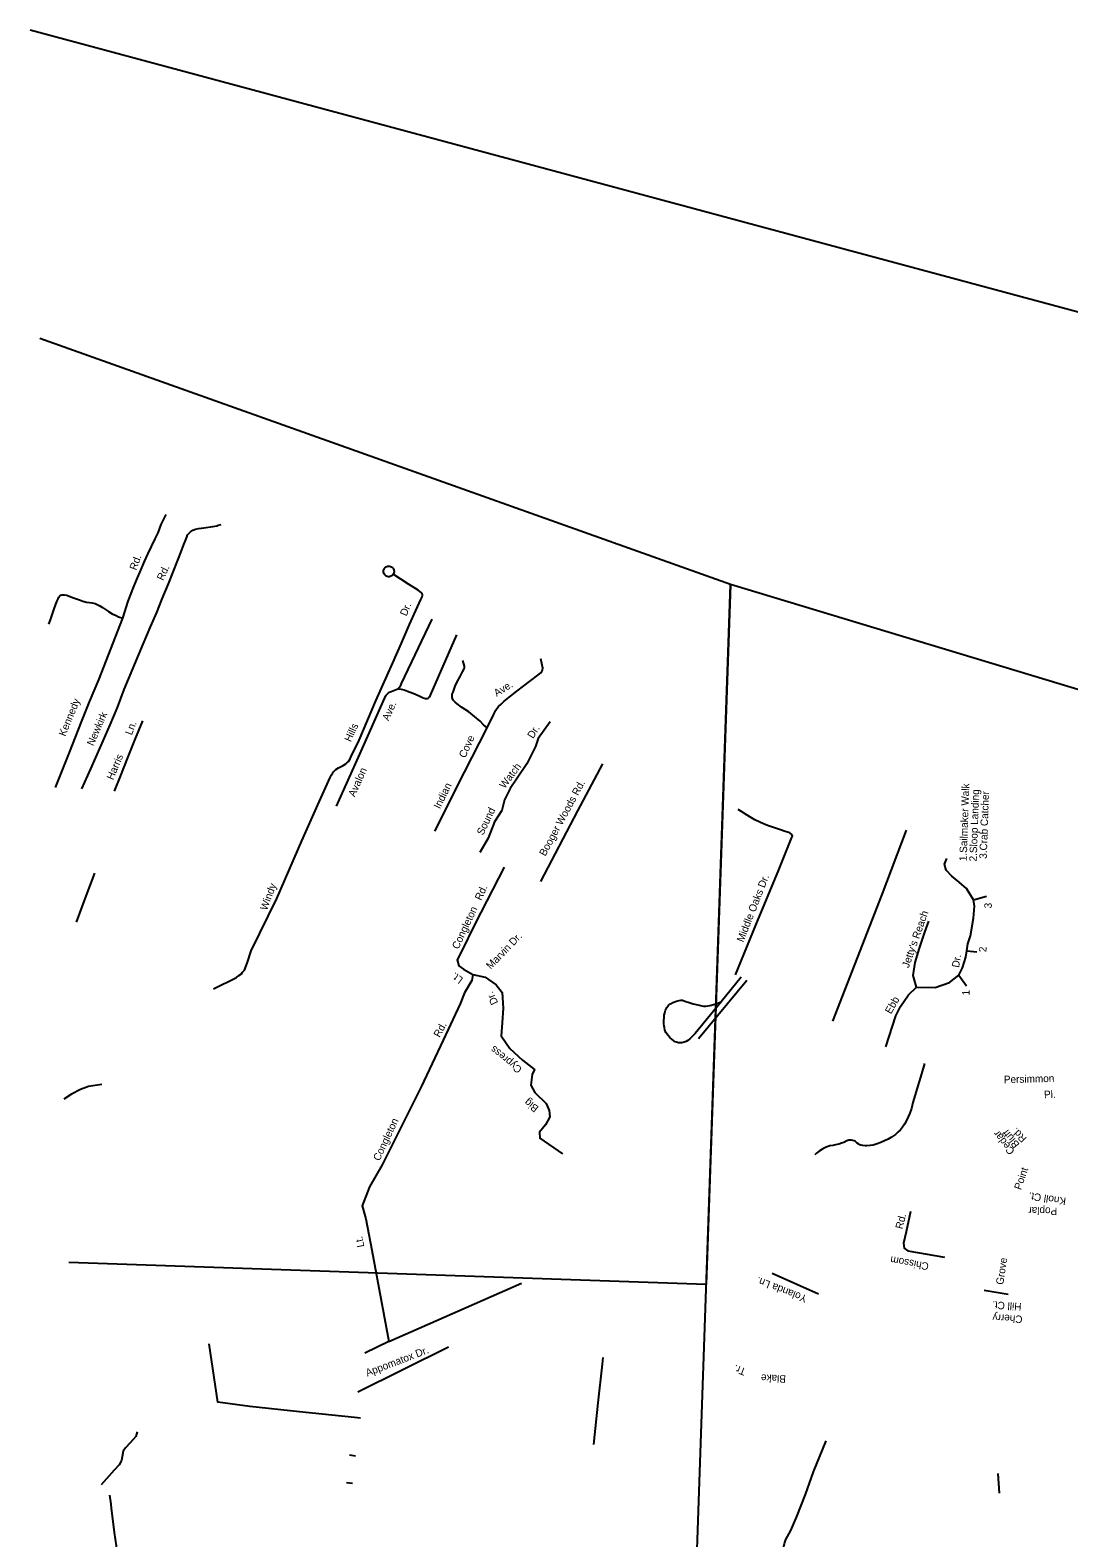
# Model space of a CAD drawing. Extents: x 2308163 to 2335412, y -96774 to 127732.
# Drawn here: x 2317411 to 2319692, y -13815 to -10505 of the extents above; entities that cross this region are included whole.
import ezdxf

# ---------------------------------------------------------------- set-up
doc = ezdxf.new("R2010")
doc.units = 0
for name, color, linetype in [('Old_Level_10', 7, 'Continuous'), ('Old_Level_35', 7, 'Continuous'), ('Old_Level_63', 7, 'Continuous')]:
    doc.layers.add(name, color=color, linetype=linetype)

msp = doc.modelspace()

# ---------------------------------------------------------------- linework, layer by layer
at = {"layer": 'Old_Level_35'}
for p, q in [((2318878.5, -12718.9), (2318984.6, -12590.9)), ((2318972.3, -12584.6), (2318928.5, -12638.1)), ((2318136.5, -13552.3), (2318123, -13551)), ((2318125.4, -13636.1), (2318112.4, -13633.7)), ((2317578.5, -13685.8), (2317566.8, -13698.8)), ((2318119, -13695.9), (2318106, -13694.6)), ((2319536.2, -13673.8), (2319538.9, -13716.9)), ((2317585.5, -13721.4), (2317587.9, -13741.7))]:
    msp.add_line(p, q, dxfattribs=at)
for points in [[(2317614.5, -11795.8), (2317626, -11758.6), (2317637.8, -11729), (2317644.8, -11712.6), (2317654, -11690.3), (2317662, -11671.6), (2317669, -11655.3), (2317685.4, -11621.7), (2317691.8, -11608.8), (2317698.9, -11590.1), (2317709.5, -11568.3)], [(2317524.4, -12170.7), (2317544.2, -12126.6), (2317565.9, -12077), (2317586.7, -12030), (2317603.1, -11991.8), (2317617.3, -11952.8), (2317659.3, -11853.2), (2317675.5, -11815), (2317688.8, -11783.4), (2317701.2, -11753.2), (2317714.7, -11720.6), (2317727.1, -11688.9), (2317741.5, -11651.9), (2317748.4, -11634.4), (2317751.9, -11625.6), (2317754.7, -11618.2), (2317756.8, -11613.3), (2317759.9, -11609.3), (2317763, -11606.4), (2317768, -11603), (2317774.2, -11600.7), (2317780.7, -11599.3), (2317787.4, -11598.4), (2317797.2, -11597.2), (2317807.2, -11595.6), (2317812.2, -11594.6), (2317820.6, -11593.1), (2317824.1, -11592.1), (2317830.7, -11590.2)], [(2318208.5, -11699.4), (2318206.9, -11701.5), (2318205.2, -11702.9), (2318203, -11704.1), (2318200.4, -11704.9), (2318197.6, -11704.9), (2318195.1, -11704.4), (2318193.1, -11703.5), (2318191.2, -11702.2), (2318189.7, -11700.7), (2318188.4, -11698.8), (2318187.6, -11697.1), (2318187.2, -11695.2), (2318187, -11693.2), (2318187.2, -11691.5), (2318187.6, -11689.5), (2318188.5, -11687.8), (2318189.6, -11686.1), (2318190.9, -11684.8), (2318192.4, -11683.6), (2318194.1, -11682.7), (2318195.7, -11682.1), (2318198, -11681.7), (2318200.2, -11681.9), (2318202.5, -11682.3), (2318204.3, -11683.1), (2318205.8, -11684.3), (2318207, -11685.2), (2318208.1, -11686.6), (2318209, -11687.9), (2318209.6, -11689.5), (2318210, -11691.2), (2318210.2, -11692.8), (2318210.2, -11694.6), (2318209.9, -11696.2), (2318209.4, -11697.8), (2318208.5, -11699.4)], [(2318042.9, -12206), (2318069.5, -12145.7), (2318072.6, -12139.7), (2318074.7, -12136.8), (2318076.7, -12133.8), (2318079.3, -12130.9), (2318082.4, -12128), (2318088, -12124.6), (2318098.1, -12119.3), (2318104.2, -12116), (2318106.7, -12113.9), (2318110.1, -12110.5), (2318113.4, -12105.2), (2318114.9, -12101.5), (2318133.3, -12064.2), (2318170, -11977.5), (2318207.6, -11894.2), (2318226.2, -11851), (2318244.1, -11809.9), (2318257.7, -11779.3), (2318268.6, -11754.7), (2318271.6, -11748.8), (2318272.3, -11745.6), (2318271.5, -11742.1), (2318269.7, -11739.8), (2318262.8, -11734.8), (2318242.1, -11721.6), (2318208.5, -11699.4)], [(2317452, -11809.2), (2317455.3, -11799.3), (2317462.8, -11777.5), (2317467.2, -11765.2), (2317470.1, -11757.8), (2317472.1, -11753.2), (2317474.1, -11749.8), (2317476.1, -11747.2), (2317478, -11745.8), (2317480.6, -11744.8), (2317482.3, -11744.6), (2317486, -11744.7), (2317491.1, -11745.7), (2317504.1, -11750.6), (2317519, -11756), (2317526.9, -11758.9), (2317534.8, -11761), (2317541.3, -11761.7), (2317547.1, -11762.4), (2317553.8, -11764.1), (2317558.2, -11765.7), (2317564.1, -11768.9), (2317570.1, -11772.8), (2317574, -11775.7), (2317582.8, -11781.5), (2317590.7, -11786.2), (2317599.6, -11790.4), (2317605, -11793.1), (2317614.5, -11795.8)], [(2317466.4, -12167.5), (2317497.1, -12090.8), (2317523.7, -12023.7), (2317541, -11979.7), (2317561.8, -11931.6), (2317614.5, -11795.8)], [(2318218.7, -11951.2), (2318221.9, -11947.6), (2318224.9, -11943.3), (2318226.5, -11939.8), (2318293.7, -11798.5)], [(2318218.7, -11951.2), (2318226.1, -11952), (2318232.1, -11953.5), (2318239.6, -11956.2), (2318253.5, -11961.5), (2318265.3, -11966.8), (2318274.3, -11971.1), (2318279.1, -11972.2), (2318282.7, -11972.3), (2318285, -11971.5), (2318286.6, -11970.5), (2318288.4, -11968.4), (2318289.9, -11965.4), (2318347.9, -11832.8)], [(2318414.3, -12037), (2318406.9, -12030.3), (2318399.1, -12022.5), (2318386.8, -12012.2), (2318374.1, -12001.9), (2318358.3, -11991.1), (2318348.5, -11984.3), (2318344, -11980.6), (2318341.6, -11977.6), (2318340.2, -11975.9), (2318338.2, -11972.6), (2318337.8, -11970.1), (2318337.4, -11967), (2318338, -11963.1), (2318339.6, -11958.5), (2318342.2, -11951.6), (2318344.5, -11945.6), (2318349.1, -11935.9), (2318355, -11923.9), (2318360.7, -11913.6), (2318363.8, -11907.2), (2318364.8, -11904), (2318364.9, -11901.2), (2318360.9, -11888.8)], [(2318414.3, -12037), (2318429, -12006.8), (2318433.7, -11997.9), (2318436.5, -11993.6), (2318439.8, -11989.8), (2318445.1, -11984.6), (2318451.7, -11978.3), (2318479.7, -11956.5), (2318525.6, -11921.5), (2318532.3, -11915.8), (2318534.4, -11913), (2318536.4, -11909.8), (2318537.1, -11905.8), (2318532.6, -11885.2)], [(2318083.4, -12209), (2318134.7, -12094.7), (2318189.7, -11970.9), (2318191.5, -11967.1), (2318192.6, -11965.4), (2318193.7, -11964.2), (2318195.1, -11962.5), (2318196.9, -11960.6), (2318198, -11959.8), (2318200.2, -11958.6), (2318218.7, -11951.2)], [(2317596.4, -12175.9), (2317608.3, -12145.3), (2317626.1, -12100.7), (2317640.9, -12064.1), (2317658.1, -12021.6)], [(2318299.7, -12263.7), (2318364.9, -12134.3), (2318414.3, -12037)], [(2318552.8, -12023.8), (2318526.4, -12060.5), (2318520.8, -12077.9), (2318501.9, -12116.1), (2318479.4, -12149.2), (2318464.8, -12170.1), (2318452.7, -12194.7), (2318446.8, -12218.4), (2318430.9, -12242.9), (2318417.1, -12278.8), (2318398.3, -12310.8)], [(2318532.6, -12373.9), (2318613.4, -12218.8), (2318669, -12116.1)], [(2317896.6, -12526.3), (2317952.5, -12411.4), (2318007.5, -12284.7), (2318042.9, -12206)], [(2318959.9, -12578.8), (2319004.5, -12470.3), (2319055, -12348.5), (2319083.3, -12278.7), (2319085.3, -12274.7), (2319083.9, -12271.2), (2319079.5, -12267.6), (2319074.5, -12266), (2319069.1, -12264.3), (2319059.2, -12260.6), (2319030.4, -12250.9), (2319024.9, -12249.3), (2319021.5, -12247.6), (2319013.6, -12244), (2319002.6, -12238.6), (2318991.8, -12232.5), (2318966.2, -12216.4)], [(2319173.5, -12681), (2319281.9, -12402.5), (2319335.3, -12261.7)], [(2318452.2, -12342.7), (2318388.6, -12466.4), (2318356.7, -12530.7), (2318348.8, -12546.5), (2318352.1, -12559), (2318362.9, -12566.8), (2318383.5, -12578.6), (2318410.5, -12584.4), (2318434.6, -12601.3), (2318447.6, -12617.8), (2318450.1, -12652.5), (2318447.8, -12684.5), (2318445.6, -12712.8), (2318464.4, -12740.6), (2318491.9, -12766.3), (2318512, -12781.5)], [(2319290.3, -12737), (2319312.5, -12669.5), (2319322.6, -12648.5), (2319340.2, -12623.1), (2319357.5, -12606.1), (2319398.3, -12606.6), (2319430.3, -12595.6), (2319450.3, -12579.6), (2319458.3, -12564.1), (2319465.6, -12540.2), (2319467.9, -12526.4), (2319470.3, -12510.7), (2319476.5, -12493.3), (2319482.5, -12454.5), (2319485.3, -12428.6), (2319482.9, -12414.6), (2319467.1, -12389.9), (2319450.9, -12375.4), (2319435.5, -12362.8), (2319423, -12349.4), (2319418.8, -12336.3), (2319423.9, -12323.5)], [(2317551.9, -12356), (2317531.9, -12409.8), (2317511.7, -12463.3)], [(2319482.9, -12414.6), (2319511.4, -12406.2)], [(2319357.5, -12606.1), (2319350, -12580.8), (2319354.7, -12552.2), (2319364.1, -12520.9), (2319375.6, -12485.1), (2319384.7, -12461.3)], [(2317813.7, -12610.2), (2317864.1, -12585.1), (2317869.4, -12580.9), (2317874.8, -12577.2), (2317877.5, -12573.3), (2317881.6, -12569.1), (2317887.4, -12553.2), (2317896.6, -12526.3)], [(2319467.9, -12526.4), (2319490.3, -12528.5)], [(2318383.5, -12578.6), (2318380.9, -12591.5), (2318365.2, -12618.6), (2318355.5, -12642.8), (2318318.2, -12722.3), (2318269.4, -12824.9), (2318183.7, -12996.2), (2318156.4, -13044.5), (2318140.2, -13086.2), (2318148.1, -13115.1), (2318161.5, -13183.4)], [(2319450.3, -12579.6), (2319467.6, -12603.5)], [(2318928.5, -12638.1), (2318871.8, -12707.7), (2318865.1, -12714.5), (2318859.9, -12719.4), (2318855.4, -12723.4), (2318852, -12725.6), (2318847.3, -12727.1), (2318842.2, -12728.2), (2318835.2, -12728.3), (2318830.8, -12727.3), (2318827.7, -12726.2), (2318820.8, -12721.3), (2318816.1, -12716.9), (2318812, -12712.4), (2318807, -12705.4), (2318804.9, -12699.6), (2318804, -12695.6), (2318803.6, -12692.1), (2318802.7, -12686.1), (2318802.5, -12679.7), (2318803, -12673), (2318803.7, -12668), (2318804.7, -12662.5), (2318806.5, -12657), (2318809.4, -12651), (2318811.2, -12647.8), (2318813.2, -12645.8), (2318817.3, -12642.9), (2318822.4, -12640), (2318830.5, -12637.2), (2318836, -12635.3), (2318840, -12634.5), (2318843.5, -12635), (2318848.9, -12636.7), (2318858.1, -12640.2), (2318867, -12643.1), (2318877.3, -12645.3), (2318885.9, -12647.1), (2318889.8, -12647.6), (2318895.2, -12647.7), (2318903.3, -12646.5), (2318914.9, -12643.2), (2318928.5, -12638.1)], [(2319375.4, -12773.9), (2319368.3, -12796.7), (2319363.4, -12813.1), (2319349.3, -12859.3), (2319346.5, -12872.8), (2319342.8, -12883.2), (2319339.5, -12891.1), (2319335.6, -12898.6), (2319331.2, -12906.9), (2319327, -12913.3), (2319322.4, -12919.2), (2319316.5, -12924.9), (2319311.1, -12929.9), (2319302.9, -12935.2), (2319295.2, -12939.7), (2319287.4, -12943.6), (2319279.4, -12947.3), (2319271.5, -12950.4), (2319262.4, -12952.9), (2319256.1, -12953.9), (2319248.5, -12954.4), (2319244.7, -12954.5), (2319240, -12954.2), (2319235.5, -12953.1), (2319233.3, -12952.1)], [(2318512, -12781.5), (2318518.4, -12786.9), (2318513.1, -12797.9), (2318510.4, -12821.5), (2318519.1, -12837.6), (2318544.2, -12861.9), (2318551.1, -12877), (2318551.9, -12890.6), (2318542.6, -12908.8), (2318529.7, -12924.4), (2318530.5, -12938), (2318580, -12971.8)], [(2317568.4, -12819.6), (2317539.3, -12824.6), (2317521.5, -12830.8), (2317501.7, -12840.8), (2317484.9, -12852.3)], [(2319233.3, -12952.1), (2319231.2, -12951.1), (2319227.1, -12948.4), (2319222.5, -12944.5), (2319220.3, -12943.4), (2319217.8, -12942.5), (2319213.8, -12942), (2319208.8, -12942.4), (2319204.2, -12943.9), (2319197.6, -12947.2), (2319192.6, -12949), (2319187.2, -12950.7), (2319180, -12952.3), (2319174, -12953.6), (2319167.4, -12954.9), (2319159, -12957.6), (2319151.8, -12961), (2319144.1, -12966.4), (2319138, -12970.7), (2319133.9, -12974.2)], [(2319344.2, -13098.5), (2319334.8, -13143.1), (2319329, -13168.3), (2319330.6, -13179.1), (2319338.2, -13185.3), (2319418.9, -13198.8)], [(2318161.5, -13183.4), (2318198.9, -13384.1), (2318145.8, -13409.9)], [(2319040.3, -13234.3), (2319142, -13279.4)], [(2318198.9, -13384.1), (2318489.9, -13256.4)], [(2319559.2, -13281.2), (2319506.1, -13272.5)], [(2318123, -13551), (2318002.7, -13538.5), (2317893.5, -13526.9), (2317823.1, -13517.7), (2317803.7, -13389.2)], [(2318130.8, -13494.6), (2318329.6, -13396)], [(2318668.9, -13419.1), (2318667.2, -13433.8), (2318657.5, -13518.8), (2318648.3, -13610.2)], [(2317646, -13582.5), (2317643.1, -13593.1), (2317630.6, -13606.6), (2317620.2, -13617.7), (2317615.2, -13625.2), (2317613.3, -13637.1), (2317611.4, -13645.2), (2317606.4, -13654.7), (2317595.5, -13666.8), (2317578.5, -13685.8)], [(2319065.6, -13837.6), (2319067.4, -13827.6), (2319070.7, -13818.6), (2319081.2, -13799.3), (2319094.4, -13768.8), (2319113.5, -13720.3), (2319131.1, -13670.2), (2319159.1, -13602.4)], [(2317587.9, -13741.7), (2317588.9, -13749.8), (2317595.6, -13803.7), (2317603.9, -13862.2), (2317608.6, -13901.1), (2317608.2, -13914.1), (2317603.3, -13926.6), (2317591.4, -13943.2), (2317578.9, -13955.8)]]:
    msp.add_lwpolyline(points, dxfattribs=at)
at = {"layer": 'Old_Level_63'}
for p, q in [((2318948.8, -11722.3), (2317432.2, -11182)), ((2320981.2, -12335.3), (2318948.8, -11722.3))]:
    msp.add_line(p, q, dxfattribs=at)
for points in [[(2324171.2, -12419.9), (2323510.7, -12146.1), (2317410.9, -10504.9)], [(2318948.8, -11722.6), (2318895.8, -13259.4), (2317496.2, -13211.1)], [(2320981.2, -12335.3), (2320867.9, -15621.3), (2318816.5, -15556.5), (2318948.8, -11722.3)]]:
    msp.add_lwpolyline(points, dxfattribs=at)

# ---------------------------------------------------------------- texts
at = {"layer": 'Old_Level_10'}
for s, height, rotation, p in [('Rd.', 16.4, 69.6167, (2317643.8, -11692)), ('Rd.', 16.4, 65.0847, (2317703, -11714.7)), ('Dr.', 16.4, 67.3169, (2318237.4, -11792.7)), ('Ave.', 16.4, 32.0499, (2318435.6, -11969)), ('Kennedy', 16.4, 67.8467, (2317488, -12056.8)), ('Ave.', 16.4, 66.0506, (2318198, -12022.8)), ('Newkirk', 16.4, 66.499, (2317549.7, -12077.7)), ('Ln.', 16.4, 69.1108, (2317634.1, -12054)), ('Hills', 16.4, 65.6411, (2318115, -12069)), ('Dr.', 16.4, 57.3171, (2318515.3, -12061.7)), ('Cove', 16.4, 65.514, (2318366.5, -12104.3)), ('Harris', 16.4, 67.3307, (2317593.2, -12152.5)), ('Avalon', 16.4, 65.8193, (2318123.5, -12189.8)), ('Watch', 16.4, 53.1139, (2318453.1, -12171.5)), ('Indian ', 16.4, 63.7995, (2318310.9, -12216)), ('Booger Woods Rd.', 16.404, 61.6242, (2318542.3, -12319.9)), ('1.Sailmaker Walk', 16.404, 88.0247, (2319467.8, -12329.8)), ('2.Sloop Landing', 16.404, 88.0247, (2319489.8, -12330.4)), ('3.Crab Catcher', 16.404, 88.0247, (2319511.8, -12324.6)), ('Sound ', 16.4, 64.3347, (2318405.7, -12273.9)), ('Windy', 16.4, 69.4786, (2317930.7, -12438.9)), ('Middle Oaks Dr.', 16.404, 68.7633, (2318977.3, -12508.7)), ('Congleton   Rd.', 16.404, 64.9615, (2318351.3, -12524.2)), ("Jetty's Reach", 16.404, 70.5106, (2319340.4, -12565.1)), ('3', 16.4, 88.0247, (2319522.7, -12433.5)), ('Marvin Dr.', 16.4, 45.8234, (2318422.4, -12568)), ('Dr.', 16.4, 80.239, (2319450.9, -12564.2)), ('2', 16.4, 88.0247, (2319511.1, -12529.7)), ('Lt.', 16.4, 143.6523, (2318363.2, -12587)), ('Dr.', 16.4, 115.5158, (2318439.1, -12640.3)), ('Ebb ', 16.4, 60.3233, (2319301.5, -12666.5)), ('1', 16.4, 88.0247, (2319473.9, -12624.6)), ('Rd.', 16.4, 61.5377, (2318310.2, -12717.9)), ('Cypress', 16.4, 140.9663, (2318492.5, -12784.2)), ('Persimmon ', 16.4, 1.5076, (2319549.6, -12817.1)), ('Pl.', 16.4, 1.5076, (2319637.8, -12850)), ('Big', 16.4, 141.4721, (2318529.1, -12869.5)), ('Congleton', 16.4, 64.9413, (2318178.1, -12989.1)), ('Cedar ', 16.4, 128.3484, (2319574.4, -12966.1)), ('Bluff', 16.4, 128.3484, (2319584.9, -12951.4)), ('Rd.', 16.4, 134.7737, (2319600.8, -12937.4)), ('Point', 16.4, 71.0018, (2319586.9, -13052.5)), ('Knoll Ct.', 16.4, 171.486, (2319686.8, -13068.8)), ('Rd.', 16.4, 75.3776, (2319326.6, -13138.5)), ('Poplar', 16.4, 178.5533, (2319666.8, -13090.3)), ('Lt. ', 16.4, 101.4483, (2318145.1, -13175.8)), ('Chissom', 16.4, 169.6256, (2319385.6, -13211.9)), ('Grove ', 16.4, 81.4647, (2319548, -13260.4)), ('Yolanda Ln.', 16.404, 158.6402, (2319118.7, -13284.4)), ('Hill Ct.', 16.4, 176.1975, (2319588.6, -13300)), ('Cherry ', 16.4, 176.1975, (2319590.8, -13327.7)), ('Appomatox Dr.', 16.404, 20.8983, (2318151.3, -13461.3)), ('Tr.', 16.4, 159.6034, (2318984.6, -13444.2)), ('Blake', 16.4, 177.5682, (2319071.1, -13458.5))]:
    msp.add_text(s, height=height, rotation=rotation, dxfattribs=at).set_placement(p)

doc.saveas('drawing.dxf')
